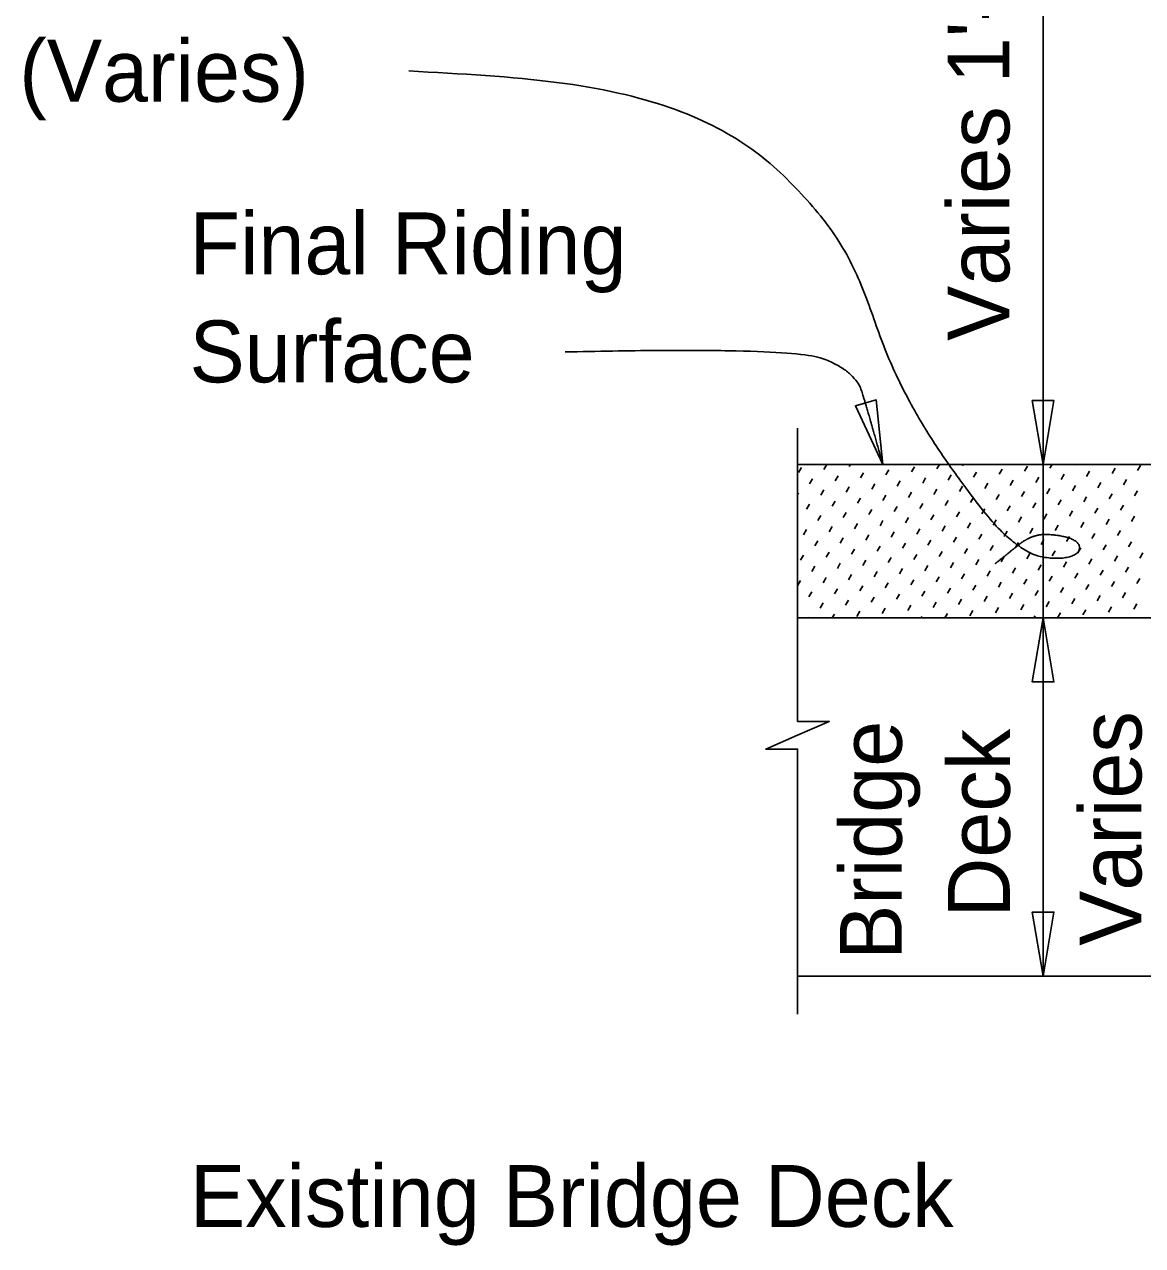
# Model space of a CAD drawing. Extents: x 21516.9 to 21589, y 56156.6 to 56194.3.
# Drawn here: x 21519.101 to 21522.743, y 56180.667 to 56184.645 of the extents above; entities that cross this region are included whole.
import ezdxf

# ---------------------------------------------------------------- set-up
doc = ezdxf.new("R2010")
doc.units = 0
for name, color, linetype in [('AdhocPoint_dp', 7, 'Continuous'), ('Patterning', 7, 'Continuous'), ('PlotBorder_dp', 7, 'Continuous'), ('SheetBorder_dp', 7, 'Continuous')]:
    doc.layers.add(name, color=color, linetype=linetype)

msp = doc.modelspace()

# ---------------------------------------------------------------- linework, layer by layer
at = {"layer": 'AdhocPoint_dp'}
for p, q in [((21525.5524, 56182.7117), (21521.6191, 56182.7117)), ((21521.6191, 56181.5451), (21528.2608, 56181.5451))]:
    msp.add_line(p, q, dxfattribs=at)
at = {"layer": 'Patterning'}
for p, q in [((21522.8378, 56183.2117), (21521.6191, 56183.2117)), ((21521.6219, 56183.1853), (21521.6316, 56183.2021)), ((21521.7048, 56183.195), (21521.7145, 56183.2117)), ((21521.7878, 56183.2047), (21521.7918, 56183.2117)), ((21521.8244, 56183.1681), (21521.8341, 56183.1849)), ((21521.9073, 56183.1778), (21521.917, 56183.1946)), ((21521.9903, 56183.1876), (21522, 56183.2044)), ((21522.0732, 56183.1973), (21522.0816, 56183.2117)), ((21522.1098, 56183.1607), (21522.1195, 56183.1775)), ((21522.1561, 56183.207), (21522.1589, 56183.2117)), ((21522.1927, 56183.1704), (21522.2025, 56183.1872)), ((21522.2757, 56183.1801), (21522.2854, 56183.1969)), ((21522.3586, 56183.1898), (21522.3683, 56183.2066)), ((21522.4416, 56183.1996), (21522.4486, 56183.2117)), ((21522.4782, 56183.163), (21522.4879, 56183.1798)), ((21522.5245, 56183.2093), (21522.5259, 56183.2117)), ((21522.5611, 56183.1727), (21522.5708, 56183.1895)), ((21522.644, 56183.1824), (21522.6538, 56183.1992)), ((21522.727, 56183.1921), (21522.7367, 56183.2089)), ((21521.6585, 56183.1487), (21521.6682, 56183.1655)), ((21521.7414, 56183.1584), (21521.7512, 56183.1752)), ((21521.7781, 56183.1218), (21521.7878, 56183.1386)), ((21521.861, 56183.1315), (21521.8707, 56183.1483)), ((21521.9439, 56183.1412), (21521.9537, 56183.158)), ((21522.0269, 56183.151), (21522.0366, 56183.1677)), ((21522.1464, 56183.1241), (21522.1561, 56183.1409)), ((21522.2293, 56183.1338), (21522.2391, 56183.1506)), ((21522.3123, 56183.1435), (21522.322, 56183.1603)), ((21522.3952, 56183.1532), (21522.4049, 56183.17)), ((21522.5148, 56183.1264), (21522.5245, 56183.1431)), ((21522.5977, 56183.1361), (21522.6074, 56183.1529)), ((21522.6806, 56183.1458), (21522.6904, 56183.1626)), ((21521.6191, 56183.1143), (21521.6219, 56183.1191)), ((21521.6951, 56183.1121), (21521.7048, 56183.1289)), ((21521.8147, 56183.0852), (21521.8244, 56183.102)), ((21521.8976, 56183.0949), (21521.9073, 56183.1117)), ((21521.9805, 56183.1046), (21521.9903, 56183.1214)), ((21522.0635, 56183.1143), (21522.0732, 56183.1311)), ((21522.183, 56183.0875), (21522.1927, 56183.1043)), ((21522.266, 56183.0972), (21522.2757, 56183.114)), ((21522.3489, 56183.1069), (21522.3586, 56183.1237)), ((21522.4318, 56183.1166), (21522.4416, 56183.1334)), ((21522.4684, 56183.08), (21522.4782, 56183.0968)), ((21522.5514, 56183.0897), (21522.5611, 56183.1065)), ((21522.6343, 56183.0995), (21522.644, 56183.1163)), ((21522.7173, 56183.1092), (21522.727, 56183.126)), ((21521.6488, 56183.0657), (21521.6585, 56183.0825)), ((21521.7317, 56183.0755), (21521.7414, 56183.0923)), ((21521.8513, 56183.0486), (21521.861, 56183.0654)), ((21521.9342, 56183.0583), (21521.9439, 56183.0751)), ((21522.0171, 56183.068), (21522.0269, 56183.0848)), ((21522.1001, 56183.0777), (21522.1098, 56183.0945)), ((21522.1367, 56183.0411), (21522.1464, 56183.0579)), ((21522.2196, 56183.0509), (21522.2293, 56183.0676)), ((21522.3026, 56183.0606), (21522.3123, 56183.0774)), ((21522.3855, 56183.0703), (21522.3952, 56183.0871)), ((21522.505, 56183.0434), (21522.5148, 56183.0602)), ((21522.588, 56183.0531), (21522.5977, 56183.0699)), ((21522.6709, 56183.0629), (21522.6806, 56183.0797)), ((21521.6854, 56183.0291), (21521.6951, 56183.0459)), ((21521.7683, 56183.0388), (21521.7781, 56183.0556)), ((21521.8049, 56183.0022), (21521.8147, 56183.019)), ((21521.8879, 56183.012), (21521.8976, 56183.0288)), ((21521.9708, 56183.0217), (21521.9805, 56183.0385)), ((21522.0538, 56183.0314), (21522.0635, 56183.0482)), ((21522.1733, 56183.0045), (21522.183, 56183.0213)), ((21522.2562, 56183.0142), (21522.266, 56183.031)), ((21522.3392, 56183.024), (21522.3489, 56183.0408)), ((21522.4221, 56183.0337), (21522.4318, 56183.0505)), ((21522.5417, 56183.0068), (21522.5514, 56183.0236)), ((21522.6246, 56183.0165), (21522.6343, 56183.0333)), ((21522.7075, 56183.0263), (21522.7173, 56183.043)), ((21521.6391, 56182.9828), (21521.6488, 56182.9996)), ((21521.722, 56182.9925), (21521.7317, 56183.0093)), ((21521.8415, 56182.9656), (21521.8513, 56182.9824)), ((21521.9245, 56182.9754), (21521.9342, 56182.9922)), ((21522.0074, 56182.9851), (21522.0171, 56183.0019)), ((21522.0904, 56182.9948), (21522.1001, 56183.0116)), ((21522.2099, 56182.9679), (21522.2196, 56182.9847)), ((21522.2928, 56182.9776), (21522.3026, 56182.9944)), ((21522.3758, 56182.9874), (21522.3855, 56183.0042)), ((21522.4587, 56182.9971), (21522.4684, 56183.0139)), ((21522.4953, 56182.9605), (21522.505, 56182.9773)), ((21522.5783, 56182.9702), (21522.588, 56182.987)), ((21522.6612, 56182.9799), (21522.6709, 56182.9967)), ((21521.6757, 56182.9462), (21521.6854, 56182.963)), ((21521.7586, 56182.9559), (21521.7683, 56182.9727)), ((21521.8782, 56182.929), (21521.8879, 56182.9458)), ((21521.9611, 56182.9387), (21521.9708, 56182.9555)), ((21522.044, 56182.9485), (21522.0538, 56182.9653)), ((21522.127, 56182.9582), (21522.1367, 56182.975)), ((21522.1636, 56182.9216), (21522.1733, 56182.9384)), ((21522.2465, 56182.9313), (21522.2562, 56182.9481)), ((21522.3294, 56182.941), (21522.3392, 56182.9578)), ((21522.4124, 56182.9508), (21522.4221, 56182.9675)), ((21522.5319, 56182.9239), (21522.5417, 56182.9407)), ((21522.6149, 56182.9336), (21522.6246, 56182.9504)), ((21522.6978, 56182.9433), (21522.7075, 56182.9601)), ((21521.6293, 56182.8999), (21521.6391, 56182.9167)), ((21521.7123, 56182.9096), (21521.722, 56182.9264)), ((21521.7952, 56182.9193), (21521.8049, 56182.9361)), ((21521.8318, 56182.8827), (21521.8415, 56182.8995)), ((21521.9148, 56182.8924), (21521.9245, 56182.9092)), ((21521.9977, 56182.9021), (21522.0074, 56182.9189)), ((21522.0806, 56182.9119), (21522.0904, 56182.9287)), ((21522.2002, 56182.885), (21522.2099, 56182.9018)), ((21522.2831, 56182.8947), (21522.2928, 56182.9115)), ((21522.3661, 56182.9044), (21522.3758, 56182.9212)), ((21522.449, 56182.9141), (21522.4587, 56182.9309)), ((21522.5685, 56182.8873), (21522.5783, 56182.9041)), ((21522.6515, 56182.897), (21522.6612, 56182.9138)), ((21522.7344, 56182.9067), (21522.7441, 56182.9235)), ((21521.6659, 56182.8633), (21521.6757, 56182.88)), ((21521.7489, 56182.873), (21521.7586, 56182.8898)), ((21521.8684, 56182.8461), (21521.8782, 56182.8629)), ((21521.9514, 56182.8558), (21521.9611, 56182.8726)), ((21522.0343, 56182.8655), (21522.044, 56182.8823)), ((21522.1172, 56182.8753), (21522.127, 56182.8921)), ((21522.2368, 56182.8484), (21522.2465, 56182.8652)), ((21522.3197, 56182.8581), (21522.3294, 56182.8749)), ((21522.4027, 56182.8678), (21522.4124, 56182.8846)), ((21522.4856, 56182.8775), (21522.4953, 56182.8943)), ((21522.5222, 56182.8409), (21522.5319, 56182.8577)), ((21522.6051, 56182.8507), (21522.6149, 56182.8674)), ((21522.6881, 56182.8604), (21522.6978, 56182.8772)), ((21521.6196, 56182.8169), (21521.6293, 56182.8337)), ((21521.7026, 56182.8266), (21521.7123, 56182.8434)), ((21521.7855, 56182.8364), (21521.7952, 56182.8532)), ((21521.905, 56182.8095), (21521.9148, 56182.8263)), ((21521.988, 56182.8192), (21521.9977, 56182.836)), ((21522.0709, 56182.8289), (21522.0806, 56182.8457)), ((21522.1539, 56182.8387), (21522.1636, 56182.8554)), ((21522.1905, 56182.802), (21522.2002, 56182.8188)), ((21522.2734, 56182.8118), (21522.2831, 56182.8286)), ((21522.3563, 56182.8215), (21522.3661, 56182.8383)), ((21522.4393, 56182.8312), (21522.449, 56182.848)), ((21522.5588, 56182.8043), (21522.5685, 56182.8211)), ((21522.6418, 56182.814), (21522.6515, 56182.8308)), ((21522.7247, 56182.8238), (21522.7344, 56182.8406)), ((21521.6562, 56182.7803), (21521.6659, 56182.7971)), ((21521.7392, 56182.79), (21521.7489, 56182.8068)), ((21521.8221, 56182.7998), (21521.8318, 56182.8166)), ((21521.8587, 56182.7632), (21521.8684, 56182.7799)), ((21521.9416, 56182.7729), (21521.9514, 56182.7897)), ((21522.0246, 56182.7826), (21522.0343, 56182.7994)), ((21522.1075, 56182.7923), (21522.1172, 56182.8091)), ((21522.2271, 56182.7654), (21522.2368, 56182.7822)), ((21522.31, 56182.7752), (21522.3197, 56182.792)), ((21522.3929, 56182.7849), (21522.4027, 56182.8017)), ((21522.4759, 56182.7946), (21522.4856, 56182.8114)), ((21522.5954, 56182.7677), (21522.6051, 56182.7845)), ((21522.6784, 56182.7774), (21522.6881, 56182.7942)), ((21521.6191, 56182.7499), (21521.6196, 56182.7508)), ((21521.6928, 56182.7437), (21521.7026, 56182.7605)), ((21521.7758, 56182.7534), (21521.7855, 56182.7702)), ((21521.8953, 56182.7265), (21521.905, 56182.7433)), ((21521.9783, 56182.7363), (21521.988, 56182.7531)), ((21522.0612, 56182.746), (21522.0709, 56182.7628)), ((21522.1441, 56182.7557), (21522.1539, 56182.7725)), ((21522.2637, 56182.7288), (21522.2734, 56182.7456)), ((21522.3466, 56182.7386), (21522.3563, 56182.7553)), ((21522.4295, 56182.7483), (21522.4393, 56182.7651)), ((21522.5125, 56182.758), (21522.5222, 56182.7748)), ((21522.5491, 56182.7214), (21522.5588, 56182.7382)), ((21522.632, 56182.7311), (21522.6418, 56182.7479)), ((21522.715, 56182.7408), (21522.7247, 56182.7576)), ((21521.6548, 56182.7117), (21521.6562, 56182.7142)), ((21521.7321, 56182.7117), (21521.7392, 56182.7239)), ((21521.8124, 56182.7168), (21521.8221, 56182.7336)), ((21522.0219, 56182.7117), (21522.0246, 56182.7165)), ((21522.0992, 56182.7117), (21522.1075, 56182.7262)), ((21522.1807, 56182.7191), (21522.1905, 56182.7359)), ((21522.3889, 56182.7117), (21522.3929, 56182.7187)), ((21522.4662, 56182.7117), (21522.4759, 56182.7285))]:
    msp.add_line(p, q, dxfattribs=at)
at = {"layer": 'PlotBorder_dp'}
msp.add_line((21522.4194, 56188.5451), (21522.4194, 56181.5451), dxfattribs=at)
for points in [[(21521.8968, 56183.2118), (21521.8755, 56183.4219), (21521.8075, 56183.4032)], [(21522.4194, 56183.2118), (21522.4547, 56183.42), (21522.3841, 56183.42)], [(21522.4194, 56182.7118), (21522.3841, 56182.5035), (21522.4547, 56182.5035)], [(21522.4194, 56181.5451), (21522.4547, 56181.7533), (21522.3841, 56181.7533)]]:
    msp.add_lwpolyline(points, close=True, dxfattribs=at)
msp.add_lwpolyline([(21521.6192, 56181.4211), (21521.6192, 56182.2845), (21521.5159, 56182.2845), (21521.6192, 56182.3295), (21521.7225, 56182.3745), (21521.6192, 56182.3745), (21521.6192, 56183.3295)], dxfattribs=at)
for points in [[(21520.3532, 56184.4939), (21521.1645, 56184.4713), (21521.7571, 56184.0192), (21521.9346, 56183.4727), (21522.2219, 56183.0503), (21522.3636, 56182.9198), (21522.4685, 56182.9014), (21522.538, 56182.9199), (21522.538, 56182.961), (21522.4671, 56182.9837), (21522.3807, 56182.9837), (21522.29, 56182.9099), (21522.263, 56182.8886)], [(21520.8624, 56183.5785), (21521.6105, 56183.5955), (21521.8073, 56183.5131), (21521.8458, 56183.397), (21521.8968, 56183.2117)]]:
    msp.add_open_spline(points, degree=2, dxfattribs=at)

# ---------------------------------------------------------------- texts
for s, p in [('(Varies)', (21519.0838, 56184.3936)), ('Final Riding ', (21519.6383, 56183.8312)), ('Surface', (21519.6383, 56183.4792))]:
    msp.add_text(s, height=0.2016, dxfattribs=at).set_placement(p)
for s, p in [('Bridge', (21521.9589, 56181.5977)), ('Deck', (21522.3109, 56181.736))]:
    msp.add_text(s, height=0.2016, rotation=90, dxfattribs=at).set_placement(p)
at = {"layer": 'SheetBorder_dp'}
for s, p in [('Varies 1\'-9" to 2\'-0"', (21522.3094, 56183.6143)), ('Varies', (21522.7396, 56181.6436))]:
    msp.add_text(s, height=0.2016, rotation=90, dxfattribs=at).set_placement(p)
msp.add_text('Existing Bridge Deck', height=0.2016, dxfattribs=at).set_placement((21519.64, 56180.7278))

doc.saveas('drawing.dxf')
